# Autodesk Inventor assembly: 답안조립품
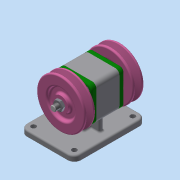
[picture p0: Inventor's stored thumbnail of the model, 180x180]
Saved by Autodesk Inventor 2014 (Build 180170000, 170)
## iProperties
Created: 2020-11
Part Number: 답안조립품
Document SubType Name: Assembly
Designer: kh
Author: kh
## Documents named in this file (10)
- C:\Users\kh\Desktop\701106V1025\답안조립품.iam
- C:\Users\kh\Desktop\701106V1025\본체.ipt
- C:\Users\kh\Desktop\701106V1025\베어링 6004.ipt
- C:\Users\kh\Desktop\701106V1025\축.ipt
- C:\Users\kh\Desktop\701106V1025\커버.ipt
- C:\Users\kh\Desktop\701106V1025\오일 실 17 30 5.ipt
- C:\Users\kh\Desktop\701106V1025\키 5 x 5 x 12.ipt
- C:\Users\kh\Desktop\701106V1025\V-벨트풀리.ipt
- C:\Users\kh\Desktop\701106V1025\너트 M10x1.ipt
- C:\Users\kh\Desktop\701106V1025\볼트 M4.ipt
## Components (2 placed, 1 different names)
1. V-벨트풀리:1 — Mate:18, Mate:19, Mate:26, Mate:27
2. V-벨트풀리:2 — Mate:20, Mate:21, Mate:23, Mate:24
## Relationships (8: Mate 8)
- Mate:18: V-벨트풀리:1
- Mate:19: V-벨트풀리:1
- Mate:20: V-벨트풀리:2
- Mate:21: V-벨트풀리:2
- Mate:23: V-벨트풀리:2
- Mate:24: V-벨트풀리:2
- Mate:26: V-벨트풀리:1
- Mate:27: V-벨트풀리:1
